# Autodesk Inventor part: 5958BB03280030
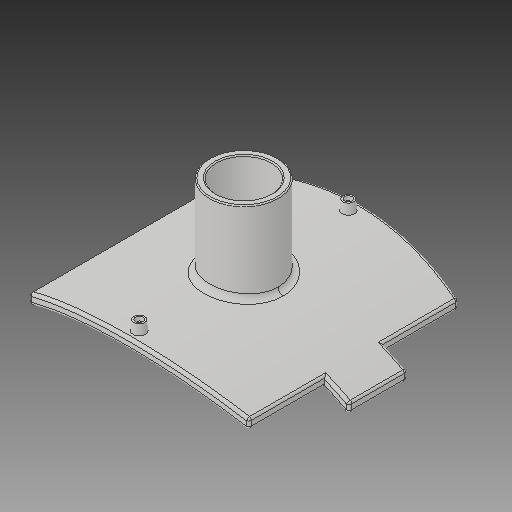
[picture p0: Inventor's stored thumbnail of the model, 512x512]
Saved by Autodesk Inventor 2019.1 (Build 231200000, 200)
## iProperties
Created: 2017-10
Part Number: 5958BB03280030
Material: Generic
Description: PLASSON BRANCH SADDLE 18''-28''IPS x 16''-24''DIPS
Document SubType Name: Modeling
Designer: KIM
Density: 1 g/cm^3
Appearance: Default
Author: KIM
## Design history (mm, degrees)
derived "5958B-1.ipt"
feature "Solid1::5958B-1.ipt"
tag "TaggingFeature1"
body "Solid1"
other parameters: "d0" = 708, "d1" = 12.954, "d2" = 283.464, "d3" = 299.974, "d4" = 0, "d5" = 314.96, "d6" = 74.9935, "d7" = 0, "d8" = 134.9883, "d10" = 0, "d11" = 3.54, "d12" = 379.6, "d13" = 14, "d14" = 134.9883, "d16" = 5 deg, "d18" = 4, "d19" = 14, "d20" = 0, "d21" = 3, "d22" = 0, "d23" = 470.84, "d24" = 88.7, "d25" = 16, "d26" = 70.96, "d28" = 0, "d29" = 9.6, "d31" = 0, "d32" = 81.788, "d33" = 0, "d34" = 7.08, "d35" = 1.416, "d_" = 708, "d_1" = 88.7, "B_" = 314.96, "H_" = 116.84, "L_" = 299.974, "x_" = 12.954, "D_" = 16, "H1" = 103.886
